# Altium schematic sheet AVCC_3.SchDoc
size 381 x 241 mm; SheetNumber: 3; SheetTotal: 3
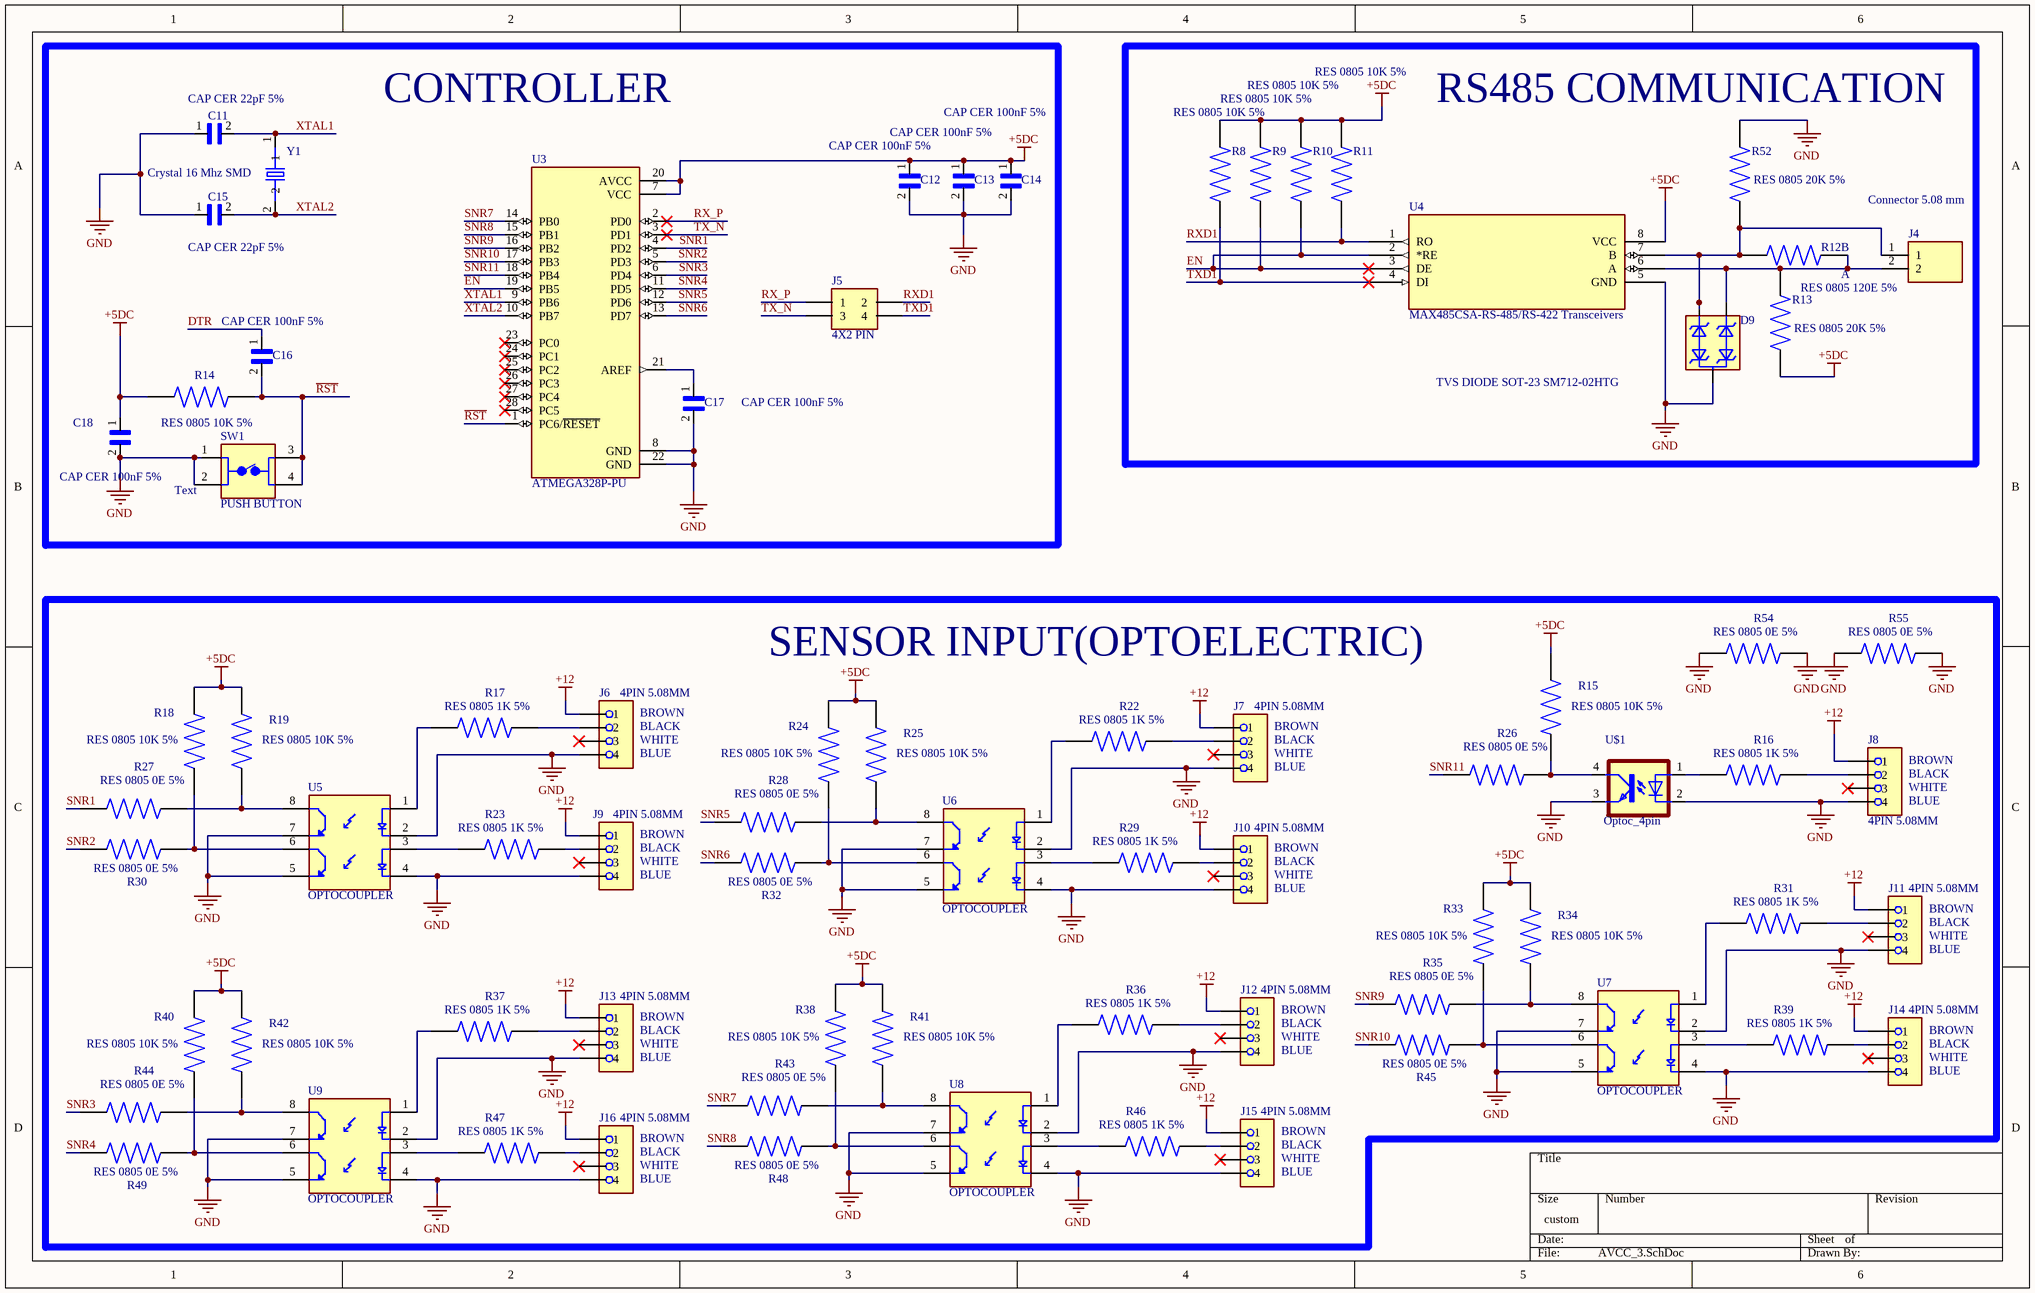
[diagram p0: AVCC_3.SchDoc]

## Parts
C11  CAP CER 22pF 5%  [CAP CER 100pF 5%]
C12  CAP CER 100nF 5%  [CAP CER 100pF 5%]
C13  CAP CER 100nF 5%  [CAP CER 100pF 5%]
C14  CAP CER 100nF 5%  [CAP CER 100pF 5%]
C15  CAP CER 22pF 5%  [CAP CER 100pF 5%]
C16  CAP CER 100nF 5%  [CAP CER 100pF 5%]
C17  CAP CER 100nF 5%  [CAP CER 100pF 5%]
C18  CAP CER 100nF 5%  [CAP CER 100pF 5%]
D9  TVS DIODE SOT-23 SM712-02HTG  [TVS Diode SOT23]
J4  Connector 5.08 mm  [Connector 5.08 mm]
J5  4X2 PIN  [4PIN BURGE]
J6  4PIN 5.08MM  [TERMINSL SCREW]
J7  4PIN 5.08MM  [TERMINSL SCREW]
J8  4PIN 5.08MM  [TERMINSL SCREW]
J9  4PIN 5.08MM  [TERMINSL SCREW]
J10  4PIN 5.08MM  [TERMINSL SCREW]
J11  4PIN 5.08MM  [TERMINSL SCREW]
J12  4PIN 5.08MM  [TERMINSL SCREW]
J13  4PIN 5.08MM  [TERMINSL SCREW]
J14  4PIN 5.08MM  [TERMINSL SCREW]
J15  4PIN 5.08MM  [TERMINSL SCREW]
J16  4PIN 5.08MM  [TERMINSL SCREW]
R8  RES 0805 10K 5%  [RES 0805 10K 5%]
R9  RES 0805 10K 5%  [RES 0805 10K 5%]
R10  RES 0805 10K 5%  [RES 0805 10K 5%]
R11  RES 0805 10K 5%  [RES 0805 10K 5%]
R12  RES 0805 120E 5%  [RES 0805 10K 5%]
R13  RES 0805 20K 5%  [RES 0805 10K 5%]
R14  RES 0805 10K 5%  [RES 0805 10K 5%]
R15  RES 0805 10K 5%  [RES 0805 10K 5%]
R16  RES 0805 1K 5%  [RES 0805 10K 5%]
R17  RES 0805 1K 5%  [RES 0805 10K 5%]
R18  RES 0805 10K 5%  [RES 0805 10K 5%]
R19  RES 0805 10K 5%  [RES 0805 10K 5%]
R22  RES 0805 1K 5%  [RES 0805 10K 5%]
R23  RES 0805 1K 5%  [RES 0805 10K 5%]
R24  RES 0805 10K 5%  [RES 0805 10K 5%]
R25  RES 0805 10K 5%  [RES 0805 10K 5%]
R26  RES 0805 0E 5%  [RES 0805 10K 5%]
R27  RES 0805 0E 5%  [RES 0805 10K 5%]
R28  RES 0805 0E 5%  [RES 0805 10K 5%]
R29  RES 0805 1K 5%  [RES 0805 10K 5%]
R30  RES 0805 0E 5%  [RES 0805 10K 5%]
R31  RES 0805 1K 5%  [RES 0805 10K 5%]
R32  RES 0805 0E 5%  [RES 0805 10K 5%]
R33  RES 0805 10K 5%  [RES 0805 10K 5%]
R34  RES 0805 10K 5%  [RES 0805 10K 5%]
R35  RES 0805 0E 5%  [RES 0805 10K 5%]
R36  RES 0805 1K 5%  [RES 0805 10K 5%]
R37  RES 0805 1K 5%  [RES 0805 10K 5%]
R38  RES 0805 10K 5%  [RES 0805 10K 5%]
R39  RES 0805 1K 5%  [RES 0805 10K 5%]
R40  RES 0805 10K 5%  [RES 0805 10K 5%]
R41  RES 0805 10K 5%  [RES 0805 10K 5%]
R42  RES 0805 10K 5%  [RES 0805 10K 5%]
R43  RES 0805 0E 5%  [RES 0805 10K 5%]
R44  RES 0805 0E 5%  [RES 0805 10K 5%]
R45  RES 0805 0E 5%  [RES 0805 10K 5%]
R46  RES 0805 1K 5%  [RES 0805 10K 5%]
R47  RES 0805 1K 5%  [RES 0805 10K 5%]
R48  RES 0805 0E 5%  [RES 0805 10K 5%]
R49  RES 0805 0E 5%  [RES 0805 10K 5%]
R52  RES 0805 20K 5%  [RES 0805 10K 5%]
R54  RES 0805 0E 5%  [RES 0805 10K 5%]
R55  RES 0805 0E 5%  [RES 0805 10K 5%]
SW1  PUSH BUTTON  [Push Button]
U3  ATMEGA328P-PU  [ATMEGA328P DIP28]
U4  MAX485CSA-RS-485/RS-422 Transceivers  [MAX485CSA-RS-485/RS-422 Transceivers]
U5  OPTOCOUPLER  [OPTOCOUPLER]
U6  OPTOCOUPLER  [OPTOCOUPLER]
U7  OPTOCOUPLER  [OPTOCOUPLER]
U8  OPTOCOUPLER  [OPTOCOUPLER]
U9  OPTOCOUPLER  [OPTOCOUPLER]
U$1  Optoc_4pin  [Optoisolator]
Y1  Crystal 16 Mhz SMD  [Crystal 16 Mhz SMD]

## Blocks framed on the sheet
CONTROLLER: C11-C18 J5 R14 SW1 U3 Y1
RS485 COMMUNICATION: D9 J4 R8-R13 R52 U4
SENSOR INPUT(OPTOELECTRIC): J6-J16 R15-R19 R22-R49 R54 R55 U5-U9 U$1

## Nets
+5DC: C12.1 C13.1 C14.1 C18.1 R8.2 R9.2 R10.2 R11.2 R13.1 R14.1 R15.2 R18.2 R19.2 R24.2 R25.2 R33.2 R34.2 R38.2 R40.2 R41.2 R42.2 U3.7(VCC) U3.20(AVCC) U4.8(VCC)
+12: J6.1 J7.1 J8.1 J9.1 J10.1 J11.1 J12.1 J13.1 J14.1 J15.1 J16.1
GND: C11.1 C12.2 C13.2 C14.2 C15.1 C17.2 C18.2 D9.3 J6.4 J7.4 J8.4 J9.4 J10.4 J11.4 J12.4 J13.4 J14.4 J15.4 J16.4 R52.2 R54.1 R54.2 R55.1 R55.2 SW1.1 SW1.2 U3.8(GND) U3.22(GND) U4.5(GND) U5.2 U5.4 U5.5 U5.7 U6.2 U6.4 U6.5 U6.7 U7.2 U7.4 U7.5 U7.7 U8.2 U8.4 U8.5 U8.7 U9.2 U9.4 U9.5 U9.7 U$1.2(C) U$1.3(EMIT)
DTR: C16.1
EN: R9.1 R10.1 U3.19(PB5) U4.2(*RE) U4.3(DE)
~{RST}: C16.2 R14.2 SW1.3 SW1.4 U3.1(PC6/~{RESET})
RX_P: J5.01(1) U3.2(PD0)
RXD1: J5.02(2) R11.1 U4.1(RO)
SNR1: R27.1 U3.4(PD2)
SNR2: R30.1 U3.5(PD3)
SNR3: R44.1 U3.6(PD4)
SNR4: R49.1 U3.11(PD5)
SNR5: R28.1 U3.12(PD6)
SNR6: R32.1 U3.13(PD7)
SNR7: R43.1 U3.14(PB0)
SNR8: R48.1 U3.15(PB1)
SNR9: R35.1 U3.16(PB2)
SNR10: R45.1 U3.17(PB3)
SNR11: R26.1 U3.18(PB4)
TX_N: J5.03(3) U3.3(PD1)
TXD1: J5.04(4) R8.1 U4.4(DI)
XTAL1: C11.2 U3.9(PB6) Y1.1
XTAL2: C15.2 U3.10(PB7) Y1.2
NetC17_1: C17.1 U3.21(AREF)
NetD9_1: D9.1 J4.2 R12.2 R13.2 U4.6(A)
NetD9_2: D9.2 J4.1 R12.1 R52.1 U4.7(B)
NetJ6_2: J6.2 R17.1
NetJ7_2: J7.2 R22.1
NetJ8_2: J8.2 R16.1
NetJ9_2: J9.2 R23.1
NetJ10_2: J10.2 R29.1
NetJ11_2: J11.2 R31.1
NetJ12_2: J12.2 R36.1
NetJ13_2: J13.2 R37.1
NetJ14_2: J14.2 R39.1
NetJ15_2: J15.2 R46.1
NetJ16_2: J16.2 R47.1
NetR15_1: R15.1 R26.2 U$1.4(COL)
NetR16_2: R16.2 U$1.1(A)
NetR17_2: R17.2 U5.1
NetR18_1: R18.1 R30.2 U5.6
NetR19_1: R19.1 R27.2 U5.8
NetR22_2: R22.2 U6.1
NetR23_2: R23.2 U5.3
NetR24_1: R24.1 R32.2 U6.6
NetR25_1: R25.1 R28.2 U6.8
NetR29_2: R29.2 U6.3
NetR31_2: R31.2 U7.1
NetR33_1: R33.1 R45.2 U7.6
NetR34_1: R34.1 R35.2 U7.8
NetR36_2: R36.2 U8.1
NetR37_2: R37.2 U9.1
NetR38_1: R38.1 R48.2 U8.6
NetR39_2: R39.2 U7.3
NetR40_1: R40.1 R49.2 U9.6
NetR41_1: R41.1 R43.2 U8.8
NetR42_1: R42.1 R44.2 U9.8
NetR46_2: R46.2 U8.3
NetR47_2: R47.2 U9.3

Not connected (* = marked no-connect by the designer): J6 3*; J7 3*; J8 3*; J9 3*; J10 3*; J11 3*; J12 3*; J13 3*; J14 3*; J15 3*; J16 3*; U3 23(PC0)* 24(PC1)* 25(PC2)* 26(PC3)* 27(PC4)* 28(PC5)*

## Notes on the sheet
- (near R12) A
- (near R12) B
- (near SW1) Text
- (near J6) BROWN
- (near J6) BLACK
- (near J6) WHITE
- (near J6) BLUE
- (near J7) BROWN
- (near J7) BLACK
- (near J7) WHITE
- (near J7) BLUE
- (near J8) BROWN
- (near J8) BLACK
- (near J9) BROWN
- (near J8) WHITE
- (near J8) BLUE
- (near J9) BLACK
- (near J9) WHITE
- (near J9) BLUE
- (near J10) BROWN
- (near J10) BLACK
- (near J10) WHITE
- (near J10) BLUE
- (near J11) BROWN
- (near J11) BLACK
- (near J11) WHITE
- (near J11) BLUE
- (near J13) BROWN
- (near J13) BLACK
- (near J13) WHITE
- (near J12) BROWN
- (near J12) BLACK
- (near J12) WHITE
- (near J14) BROWN
- (near J14) BLACK
- (near J13) BLUE
- (near J12) BLUE
- (near J14) WHITE
- (near J14) BLUE
- (near J16) BROWN
- (near J16) BLACK
- (near J16) WHITE
- (near J16) BLUE
- (near J15) BROWN
- (near J15) BLACK
- (near J15) WHITE
- (near J15) BLUE

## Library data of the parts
C11-C18 = CAP CER 100pF 5%: CAP CER 100PF50V X7R 0805; MP: GCJ216R71H222KA01D
D9 = TVS DIODE SOT-23 SM712-02HTG: TVS Diode, SM712 Series, 31V Clamp, 600W Peak Pulse, Surface Mount,Bi-Directional, SOT23-3 ¦ Littelfuse SM712-02HTG; MF: Littelfuse Inc.
J4 = Connector 5.08 mm: MOLEX,Screw Type, Horizontal, 5.08 Pitch, 24~12 (AWG), Terminal Block Connector; MF: Same Sky; MP: TB007-508-02BE
J5 = 4PIN BURGE: Connector Header Through Hole 4 position 0.100 (2.54mm), 4X2 PIN; MF: Samtec; MP: MTLW-102-05-G-D-180
J6-J16 = TERMINSL SCREW: TERMINSL SCREW, 4PIN, 5.08MM; MF: {'manufacturer': u'Phoenix Contact'}; MP: 1995664
R8-R19 R22-R49 R52 R54 R55 = RES 0805 10K 5%: RESISTOR, THICK FILM, 10K, 5%, 0805, FRESISTOR, THICK FILM, 10K, 5%, 0805, FULL REEL Product Range:PANASONIC - ERJ Series; MP: ERJ-6GEYJ103V; MF: Panasonic Electronic
SW1 = PUSH BUTTON: Switch Push Button OFF (ON) SPST Round Button 0.05A 24VDC Momentary Contact PC Pins Thru-Hole; MF: TE Connectivity; MP: 3-1825910-1
U3 = ATMEGA328P-PU: ATmega Series 20 MHz 32 KB Flash 2 KB SRAM 8-Bit Microcontroller - DIP-28
U4 = MAX485CSA-RS-485/RS-422 Transceivers: Low-Power, Slew-Rate-Limited RS-485/RS-422 Transceivers; MF: Analog Devices; MP: MAX485CSA+
U5-U9 = OPTOCOUPLER: TLP521-2,Optoisolateur Ã  sortie transistor 5300 Vrms 2 canaux 8 DIP; MF: Toshiba
U$1 = Optoc_4pin: TLP521-1,Optoisolator Transistor Output 5300Vrms 1 Channel 4-DIP; MF: Isocom
Y1 = Crystal 16 Mhz SMD: 16 Mhz Crystal SMD –CSM-4ALX(28ALX) 12.5mmX4.85mmX4mm; MF: Fox Electronics; MP: FOXSDLF/128-20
